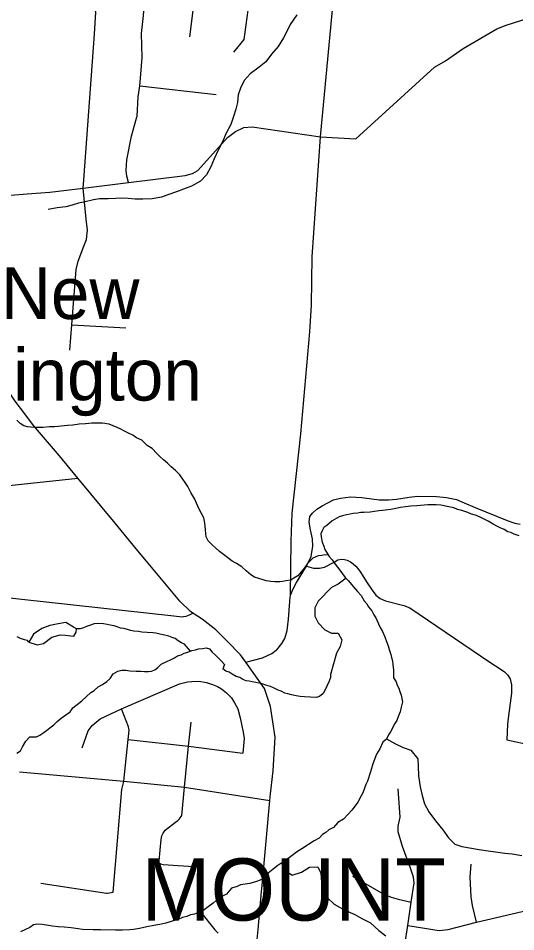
# Model space of a CAD drawing. Extents: x 0 to 69.5, y -4.5 to 22.
# Drawn here: x 6.214 to 6.973, y 17.057 to 18.449 of the extents above; entities that cross this region are included whole.
import ezdxf

# ---------------------------------------------------------------- set-up
doc = ezdxf.new("R2010")
doc.units = 0
for name, color, linetype in [('GM_X_Corporation_Text', 7, 'Continuous'), ('GM_X_County_Road', 7, 'Continuous'), ('GM_X_Minor_Lake', 7, 'Continuous'), ('GM_X_Minor_River', 7, 'Continuous'), ('GM_X_Township_Subdivision', 7, 'Continuous'), ('GM_X_Unincorporated_Text', 7, 'Continuous'), ('GM_X_US_Route', 7, 'Continuous')]:
    doc.layers.add(name, color=color, linetype=linetype)

msp = doc.modelspace()

# ---------------------------------------------------------------- linework, layer by layer
at = {"layer": 'GM_X_County_Road'}
for points in [[(6.6289, 17.5702), (6.6299, 17.6523), (6.6319, 17.6948), (6.6451, 17.8156), (6.6585, 17.9713), (6.6613, 18.0126), (6.6624, 18.0856), (6.6748, 18.2683), (6.7103, 18.6453), (6.7239, 18.8027), (6.734, 18.8917), (6.7405, 19.0079)], [(6.6748, 18.2683), (6.7285, 18.2655), (6.8486, 18.3747), (6.8655, 18.3843), (6.8923, 18.4031), (6.9436, 18.4327), (6.9578, 18.4383), (6.9913, 18.4492), (7.0954, 18.4834), (7.0971, 18.484)], [(6.063, 18.1333), (6.1136, 18.1511), (6.1283, 18.1584), (6.17, 18.1715), (6.2024, 18.1796), (6.2275, 18.1814), (6.2621, 18.1839), (6.3129, 18.1902), (6.3819, 18.1988), (6.4683, 18.2096), (6.4798, 18.2126), (6.4879, 18.217), (6.533, 18.2673), (6.545, 18.2764), (6.5577, 18.2825), (6.5706, 18.2836), (6.6748, 18.2683)], [(6.6282, 17.5603), (6.6283, 17.5621), (6.6289, 17.5702), (6.633, 17.5796), (6.6382, 17.5893), (6.6534, 17.6142), (6.6608, 17.6291), (6.663, 17.6446), (6.6626, 17.6559), (6.6596, 17.6696), (6.6576, 17.6814), (6.6584, 17.6899), (6.6626, 17.695), (6.6695, 17.7008), (6.6773, 17.7062), (6.6946, 17.7151), (6.7055, 17.7177), (6.7206, 17.7197), (6.738, 17.7187), (6.7642, 17.7153), (6.7787, 17.7154), (6.7909, 17.7162), (6.81, 17.7191), (6.8227, 17.7208), (6.8517, 17.7202), (6.8672, 17.7188), (6.8821, 17.7156), (6.8941, 17.7107), (6.9106, 17.7038), (6.9593, 17.6839), (6.9714, 17.6796), (6.9791, 17.6783)], [(5.5312, 17.5084), (5.5691, 17.507), (5.6976, 17.4979), (5.7449, 17.494), (5.7812, 17.4914), (5.8077, 17.4899), (5.8238, 17.4905), (5.8392, 17.4936), (5.8617, 17.5004), (5.9034, 17.5131), (5.9959, 17.5435), (6.0061, 17.5479), (6.0184, 17.5562), (6.041, 17.5742), (6.0478, 17.5777), (6.0541, 17.5801), (6.0612, 17.5813), (6.0695, 17.5816), (6.1446, 17.5721), (6.4513, 17.5386)], [(6.607, 17.486), (6.6073, 17.4862), (6.6082, 17.4869), (6.6157, 17.4962), (6.6204, 17.504), (6.6242, 17.5161), (6.6263, 17.5335), (6.6282, 17.5603)], [(6.4513, 17.5386), (6.4638, 17.5372), (6.4661, 17.5373), (6.47, 17.538), (6.4727, 17.5389), (6.4763, 17.5404), (6.4804, 17.5426)], [(6.5612, 17.4679), (6.5866, 17.4743), (6.6008, 17.481), (6.607, 17.486)]]:
    msp.add_lwpolyline(points, dxfattribs=at)
at = {"layer": 'GM_X_Minor_Lake'}
for points in [[(6.3028, 17.5185), (6.2984, 17.5211), (6.2864, 17.5282), (6.2746, 17.5262), (6.262, 17.5238), (6.2501, 17.5191), (6.237, 17.5106), (6.2303, 17.4982), (6.2428, 17.4945), (6.2523, 17.4966), (6.2651, 17.5058)], [(6.2651, 17.5058), (6.2777, 17.5098), (6.2857, 17.5092), (6.2989, 17.5074), (6.3021, 17.5134), (6.3028, 17.5185)]]:
    msp.add_lwpolyline(points, dxfattribs=at)
at = {"layer": 'GM_X_Minor_River'}
for points in [[(6.639, 18.4543), (6.6288, 18.4397), (6.6237, 18.4291), (6.6185, 18.419), (6.6103, 18.4059), (6.6002, 18.3943), (6.5916, 18.3827), (6.5812, 18.3745), (6.5676, 18.3642), (6.5583, 18.3541), (6.5528, 18.3424), (6.5491, 18.3322), (6.5481, 18.3205), (6.5456, 18.3107), (6.542, 18.2993), (6.5379, 18.2873), (6.5304, 18.273), (6.526, 18.262), (6.5181, 18.247), (6.5129, 18.2349), (6.5077, 18.2225), (6.501, 18.2105), (6.4921, 18.2008), (6.4779, 18.1931), (6.466, 18.1884), (6.4553, 18.1844), (6.4423, 18.1798), (6.4323, 18.1762), (6.4182, 18.1738), (6.4038, 18.1733), (6.3924, 18.1736), (6.3814, 18.1742), (6.3719, 18.1747), (6.3624, 18.1742), (6.3513, 18.174), (6.338, 18.1739), (6.3285, 18.1722), (6.3159, 18.1694), (6.3056, 18.1674), (6.296, 18.1641), (6.2865, 18.1617), (6.2732, 18.16), (6.2594, 18.1577)], [(6.6867, 17.6307), (6.6814, 17.6312), (6.6768, 17.6305), (6.6711, 17.6299), (6.6631, 17.6262), (6.6549, 17.618), (6.6506, 17.6116), (6.646, 17.606), (6.6401, 17.5993), (6.6344, 17.596), (6.6298, 17.593), (6.6221, 17.5917), (6.6176, 17.591), (6.6126, 17.5903), (6.6054, 17.5901), (6.599, 17.5906), (6.5922, 17.5919), (6.5873, 17.5935), (6.5744, 17.5976), (6.5684, 17.6011), (6.5613, 17.6069), (6.555, 17.6132), (6.5468, 17.6183), (6.5404, 17.6218), (6.5355, 17.6253), (6.531, 17.6289), (6.5206, 17.6367), (6.5146, 17.6421), (6.5101, 17.6464), (6.5034, 17.653), (6.5005, 17.6591), (6.4996, 17.669), (6.499, 17.6755), (6.498, 17.6828), (6.4969, 17.6877), (6.4933, 17.6946), (6.4896, 17.7012), (6.486, 17.71), (6.4831, 17.7162), (6.4802, 17.7215), (6.4772, 17.7265), (6.4728, 17.7354), (6.4684, 17.7415), (6.4647, 17.7469), (6.4603, 17.7535), (6.4536, 17.7601), (6.4469, 17.7656), (6.4413, 17.771), (6.4353, 17.7764), (6.4301, 17.7811), (6.4253, 17.7858), (6.4182, 17.7935), (6.4107, 17.7979), (6.4022, 17.8064), (6.3943, 17.8096), (6.3887, 17.8139), (6.3819, 17.8167), (6.3762, 17.8198), (6.3702, 17.823), (6.365, 17.8254), (6.3526, 17.8306), (6.3423, 17.8319), (6.3359, 17.8321), (6.326, 17.8319), (6.3214, 17.8316), (6.3165, 17.8313), (6.307, 17.8304), (6.2971, 17.829), (6.2891, 17.8284), (6.2842, 17.8278), (6.275, 17.8272), (6.2693, 17.8265), (6.2617, 17.8263), (6.2519, 17.8257), (6.2443, 17.8255), (6.239, 17.8256), (6.2333, 17.8261), (6.228, 17.8266), (6.2223, 17.8282), (6.2171, 17.8318), (6.2118, 17.8364)], [(6.9777, 17.6602), (6.9702, 17.663), (6.9653, 17.6654), (6.9604, 17.6667), (6.9547, 17.6698), (6.9491, 17.6726), (6.9446, 17.6746), (6.9382, 17.6781), (6.9307, 17.6825), (6.9254, 17.6852), (6.9206, 17.688), (6.9127, 17.6912), (6.9051, 17.6936), (6.8995, 17.696), (6.8904, 17.6992), (6.884, 17.7005), (6.878, 17.7029), (6.8704, 17.7046), (6.8583, 17.7071), (6.8515, 17.7076), (6.8432, 17.7078), (6.8386, 17.7075), (6.8329, 17.7072), (6.8219, 17.7059), (6.8127, 17.7054), (6.8044, 17.7044), (6.7968, 17.7034), (6.7895, 17.702), (6.7819, 17.7007), (6.7773, 17.7), (6.7693, 17.699), (6.7636, 17.6987), (6.7507, 17.6967), (6.7408, 17.6962), (6.7362, 17.6959), (6.7313, 17.6948), (6.7248, 17.6942), (6.7199, 17.6932), (6.7145, 17.6925), (6.7084, 17.6907), (6.7031, 17.6893), (6.6927, 17.6834), (6.6846, 17.6764), (6.68, 17.673), (6.6776, 17.6681), (6.6756, 17.6632), (6.6759, 17.6587), (6.6773, 17.651), (6.6798, 17.6449), (6.6816, 17.6395), (6.6882, 17.6287), (6.6926, 17.6237), (6.6956, 17.6191), (6.7008, 17.6129), (6.7045, 17.6083), (6.7126, 17.5971), (6.7178, 17.592), (6.7248, 17.5831), (6.7311, 17.5758), (6.7367, 17.5696), (6.7415, 17.5615), (6.7456, 17.5569), (6.7481, 17.5522), (6.7529, 17.5461), (6.7562, 17.5399), (6.7592, 17.5353), (6.7632, 17.5265), (6.7661, 17.5207), (6.7694, 17.5145), (6.773, 17.5065), (6.7755, 17.4996), (6.778, 17.4927), (6.7798, 17.4873), (6.782, 17.4797), (6.783, 17.4751), (6.7848, 17.4697), (6.7851, 17.4636), (6.786, 17.4564)], [(6.714, 17.5957), (6.702, 17.5866), (6.6918, 17.5815), (6.6713, 17.561), (6.6661, 17.5507), (6.6661, 17.5379), (6.6713, 17.5276), (6.6815, 17.5174), (6.6918, 17.5122), (6.702, 17.5122), (6.7072, 17.502), (6.7046, 17.4917), (6.6995, 17.4814), (6.6902, 17.449)], [(6.4765, 17.4848), (6.4676, 17.4955), (6.4631, 17.4975), (6.4578, 17.5006), (6.4533, 17.5038), (6.4488, 17.5057), (6.4435, 17.5074), (6.4349, 17.5098), (6.4299, 17.5107), (6.4239, 17.5119), (6.4194, 17.5124), (6.4106, 17.513), (6.4023, 17.5135), (6.3974, 17.5144), (6.3902, 17.5153), (6.3853, 17.5161), (6.3804, 17.5178), (6.3747, 17.519), (6.3698, 17.5199), (6.3649, 17.5219), (6.36, 17.5235), (6.3543, 17.5244), (6.3494, 17.5252), (6.3437, 17.5261), (6.3369, 17.5266), (6.3297, 17.5264), (6.3224, 17.5239), (6.3178, 17.5224), (6.3132, 17.5202), (6.3083, 17.5188), (6.3033, 17.5185), (6.3028, 17.5185)], [(6.2303, 17.4982), (6.2278, 17.501), (6.2233, 17.5019), (6.2172, 17.5039), (6.2124, 17.5067)], [(6.4317, 17.465), (6.4413, 17.4694), (6.4462, 17.4716), (6.452, 17.4745), (6.457, 17.4774), (6.4623, 17.4792), (6.4669, 17.4814), (6.4723, 17.4832), (6.4788, 17.4857), (6.4841, 17.4868), (6.4887, 17.4882), (6.4948, 17.4889), (6.5005, 17.4895), (6.5054, 17.4883), (6.5095, 17.4832), (6.5143, 17.4793), (6.5244, 17.4689), (6.5285, 17.4642), (6.5258, 17.4578)], [(6.786, 17.4564), (6.7863, 17.444), (6.7903, 17.4378), (6.7917, 17.4328), (6.7942, 17.4282), (6.7956, 17.4232), (6.7977, 17.4178), (6.7987, 17.4128), (6.7997, 17.4075), (6.798, 17.3992), (6.7963, 17.3924), (6.7938, 17.3863), (6.7914, 17.3788), (6.7882, 17.3743), (6.7814, 17.3619), (6.7786, 17.3574), (6.7754, 17.3507), (6.7699, 17.3462), (6.7651, 17.3361), (6.7603, 17.3279), (6.7546, 17.3132), (6.7512, 17.3007), (6.7463, 17.2864), (6.7442, 17.2815), (6.7393, 17.2687), (6.7369, 17.2642), (6.7317, 17.2548), (6.7234, 17.2428), (6.7097, 17.2287), (6.7012, 17.2236), (6.6945, 17.2162), (6.6876, 17.2126), (6.6829, 17.2082), (6.6779, 17.2053), (6.6728, 17.1997), (6.6651, 17.1957), (6.6465, 17.1837), (6.6384, 17.1782), (6.6318, 17.1734), (6.6221, 17.1661), (6.6097, 17.158), (6.605, 17.1544), (6.5949, 17.1463), (6.5898, 17.1392), (6.5828, 17.1359), (6.5771, 17.1338), (6.5671, 17.1307), (6.553, 17.1284), (6.5476, 17.1263), (6.5391, 17.1235), (6.5313, 17.1145), (6.5201, 17.1088), (6.5111, 17.1006), (6.5034, 17.0951), (6.4952, 17.0889), (6.4829, 17.0839), (6.4764, 17.0829), (6.471, 17.0804), (6.4642, 17.0791), (6.458, 17.0758), (6.45, 17.0738), (6.4392, 17.0703), (6.43, 17.0682), (6.4209, 17.0666), (6.4098, 17.0646), (6.399, 17.0619), (6.3899, 17.0606), (6.3842, 17.06), (6.3727, 17.0596), (6.3621, 17.0595), (6.3393, 17.0601), (6.3283, 17.06), (6.3119, 17.0605), (6.3055, 17.0614), (6.2945, 17.0633), (6.2839, 17.0639), (6.2748, 17.0646), (6.2664, 17.0656), (6.26, 17.0665), (6.2502, 17.0683), (6.2422, 17.0689), (6.2372, 17.0675), (6.2314, 17.0635), (6.2175, 17.057)], [(6.2866, 17.3876), (6.2932, 17.3923), (6.2971, 17.3983), (6.3037, 17.4034), (6.3107, 17.409), (6.3244, 17.4219), (6.3298, 17.4248), (6.336, 17.4303), (6.3426, 17.434), (6.3488, 17.4387), (6.3539, 17.4432), (6.3586, 17.4499), (6.366, 17.4543), (6.3717, 17.4556), (6.3778, 17.4558), (6.3842, 17.4549), (6.3937, 17.4542), (6.4009, 17.454), (6.4066, 17.4535), (6.4127, 17.4537), (6.4173, 17.4544), (6.4223, 17.4561), (6.427, 17.4598), (6.4317, 17.465)], [(6.6902, 17.449), (6.6901, 17.4444), (6.688, 17.4388), (6.6844, 17.4313), (6.682, 17.426), (6.6788, 17.4204), (6.6733, 17.4156), (6.6687, 17.4142), (6.6596, 17.4144), (6.6505, 17.4151), (6.6437, 17.4157), (6.638, 17.4166), (6.6304, 17.4179), (6.6251, 17.4196), (6.6206, 17.4205), (6.615, 17.4237), (6.6101, 17.4254), (6.6033, 17.429), (6.5988, 17.4306), (6.5917, 17.4327), (6.586, 17.4348), (6.5807, 17.4361), (6.5762, 17.437), (6.5709, 17.4379), (6.5663, 17.4388), (6.5614, 17.4397), (6.5562, 17.4417), (6.5517, 17.4445), (6.546, 17.4462), (6.54, 17.4498), (6.5355, 17.4526), (6.5303, 17.4542), (6.5258, 17.4578)], [(6.2116, 17.3291), (6.2174, 17.3327), (6.2202, 17.3391), (6.2254, 17.3477), (6.2317, 17.354), (6.2362, 17.3539), (6.2419, 17.3541), (6.247, 17.3567), (6.2516, 17.3596), (6.257, 17.364), (6.2621, 17.3677), (6.2683, 17.3724), (6.2734, 17.3773), (6.2796, 17.3828), (6.2866, 17.3876)], [(6.7756, 17.3511), (6.789, 17.3433), (6.8011, 17.3378), (6.8128, 17.3337), (6.8235, 17.3206), (6.8236, 17.3095), (6.8245, 17.2947), (6.8267, 17.2779), (6.8299, 17.2646), (6.8334, 17.252), (6.84, 17.2397), (6.8503, 17.2261), (6.8614, 17.2126), (6.8703, 17.2003), (6.8795, 17.1906), (6.8905, 17.1869), (6.917, 17.1825), (6.9306, 17.1803), (6.9416, 17.179), (6.956, 17.1771), (6.9674, 17.1757), (6.9821, 17.1735)], [(6.6154, 17.1618), (6.6219, 17.1502), (6.6316, 17.1435), (6.6461, 17.1477), (6.6581, 17.1555), (6.671, 17.1563), (6.6753, 17.1464), (6.6766, 17.1326), (6.6804, 17.1189), (6.6859, 17.1081), (6.6956, 17.0992), (6.7121, 17.0901), (6.7272, 17.0833), (6.7377, 17.0774), (6.7512, 17.0706), (6.7639, 17.0593), (6.7743, 17.0511)], [(6.4918, 17.0875), (6.5135, 17.0602), (6.519, 17.0551)]]:
    msp.add_lwpolyline(points, dxfattribs=at)
at = {"layer": 'GM_X_Township_Subdivision'}
for points in [[(6.3138, 18.2028), (6.3304, 18.425), (6.3322, 18.4584), (6.3274, 18.4859)], [(6.4018, 18.3765), (6.403, 18.3892), (6.4017, 18.4257), (6.4051, 18.4532), (6.4066, 18.4741), (6.4072, 18.4851), (6.4112, 18.4906), (6.4207, 18.4906), (6.4366, 18.4888), (6.4562, 18.4863), (6.4832, 18.4817), (6.5659, 18.4725), (6.5944, 18.4771)], [(6.4758, 18.4205), (6.4832, 18.4817)], [(6.5429, 18.3975), (6.5583, 18.4168), (6.5659, 18.4725)], [(6.3944, 18.2969), (6.3953, 18.2999), (6.397, 18.3293), (6.3991, 18.3459), (6.4013, 18.3699), (6.4018, 18.3765)], [(6.3991, 18.3459), (6.5156, 18.3328)], [(6.3819, 18.1988), (6.3795, 18.2083), (6.3787, 18.2169), (6.3795, 18.2334), (6.3866, 18.2693), (6.3915, 18.2879), (6.3933, 18.2934), (6.3944, 18.2969)], [(6.2927, 17.9432), (6.2957, 17.9819), (6.3025, 18.0664), (6.3051, 18.0789), (6.3138, 18.1018), (6.3179, 18.1119), (6.3194, 18.1259), (6.3177, 18.1431), (6.3129, 18.1902), (6.3138, 18.2028), (6.3138, 18.2028)], [(6.2957, 17.9819), (6.3778, 17.9775)], [(6.022, 17.7199), (6.0333, 17.7203), (6.0558, 17.7219), (6.305, 17.7484)], [(6.6534, 17.6142), (6.6641, 17.611), (6.6733, 17.6109), (6.6812, 17.6129), (6.6957, 17.6204), (6.7014, 17.6238), (6.707, 17.6247), (6.7113, 17.6242), (6.7153, 17.6231), (6.7208, 17.6209), (6.7249, 17.6176), (6.7287, 17.6142), (6.7318, 17.6105), (6.7357, 17.6052), (6.7448, 17.5901), (6.7534, 17.5774), (6.7593, 17.5701), (6.7657, 17.5649), (6.774, 17.5616), (6.8017, 17.5545), (6.811, 17.5506), (6.9333, 17.468), (6.949, 17.4576), (6.9557, 17.4533), (6.9602, 17.4488), (6.9641, 17.4423), (6.966, 17.4334), (6.9663, 17.4208), (6.9605, 17.3786)], [(6.3116, 17.3375), (6.3208, 17.3633), (6.3268, 17.3712), (6.3389, 17.3814), (6.3713, 17.3969), (6.4596, 17.4348), (6.4721, 17.4381), (6.4784, 17.4387), (6.4894, 17.4388), (6.5012, 17.4371), (6.5103, 17.4341), (6.5176, 17.431), (6.5239, 17.4271), (6.5317, 17.4211), (6.539, 17.4137), (6.5439, 17.4061), (6.5488, 17.3969), (6.5523, 17.3829), (6.557, 17.3613), (6.5583, 17.3518), (6.5565, 17.3292)], [(6.3742, 17.2843), (6.3747, 17.2864), (6.3817, 17.3502), (6.3823, 17.3546), (6.383, 17.3642), (6.3822, 17.3696), (6.3713, 17.3969)], [(6.4887, 17.1557), (6.4348, 17.1593), (6.4308, 17.1599), (6.4289, 17.1618), (6.4287, 17.1653), (6.432, 17.1977), (6.4331, 17.2031), (6.4351, 17.2074), (6.4382, 17.2119), (6.4537, 17.2239), (6.4572, 17.2269), (6.4598, 17.2292), (6.4634, 17.2344), (6.4676, 17.2776), (6.4737, 17.3397), (6.4774, 17.3767)], [(6.9605, 17.3786), (6.9598, 17.3731), (6.9592, 17.3497)], [(6.3817, 17.3502), (6.4737, 17.3397), (6.5565, 17.3292)], [(6.9592, 17.3497), (6.997, 17.3415), (7.0662, 17.3297), (7.0999, 17.3233)], [(6.216, 17.3009), (6.3747, 17.2864), (6.4676, 17.2776), (6.5974, 17.257)], [(6.3586, 17.1174), (6.3719, 17.2737), (6.3742, 17.2843)], [(6.7844, 16.9112), (6.7902, 16.9495), (6.799, 17.0076), (6.8079, 17.0668), (6.8133, 17.1023), (6.8178, 17.1319), (6.8167, 17.1402), (6.8123, 17.154), (6.8001, 17.1868), (6.7932, 17.2092), (6.7932, 17.218), (6.7964, 17.2316), (6.7931, 17.275)], [(6.9126, 17.0718), (6.9066, 17.0971), (6.9044, 17.1101), (6.9031, 17.1405), (6.9045, 17.1601)], [(6.7238, 17.1416), (6.7702, 17.1147), (6.7826, 17.11), (6.7935, 17.1067), (6.8133, 17.1023)], [(6.2483, 17.1314), (6.3486, 17.116)], [(6.8079, 17.0668), (6.8559, 17.059), (6.8697, 17.0604), (6.9126, 17.0718), (6.9976, 17.0915), (7.0535, 17.1074), (7.0787, 17.1167), (7.0879, 17.1194), (7.1083, 17.126), (7.1159, 17.1268), (7.1214, 17.127), (7.1302, 17.1268), (7.1611, 17.1219), (7.2871, 17.0984), (7.3191, 17.0935)], [(6.3486, 17.116), (6.3502, 17.1157), (6.3586, 17.1174)]]:
    msp.add_lwpolyline(points, dxfattribs=at)
at = {"layer": 'GM_X_US_Route'}
for points in [[(6.3964, 17.6376), (6.3615, 17.6796), (6.305, 17.7484), (6.277, 17.7824), (6.2372, 17.8287), (6.224, 17.8461), (6.2093, 17.8655), (6.1706, 17.9227), (6.1378, 17.9744), (6.1043, 18.0396)], [(6.5857, 17.1275), (6.5974, 17.257), (6.5985, 17.2671), (6.6027, 17.3024), (6.6056, 17.3535), (6.5985, 17.4006), (6.5894, 17.4276), (6.5612, 17.4679), (6.5528, 17.4791), (6.5325, 17.4997), (6.5155, 17.5173), (6.4943, 17.5334), (6.4804, 17.5426), (6.4764, 17.5452), (6.4601, 17.5608), (6.4096, 17.6217), (6.3964, 17.6376)], [(6.5713, 16.9682), (6.5773, 17.0352), (6.5796, 17.0608), (6.5848, 17.1183), (6.5857, 17.1275)]]:
    msp.add_lwpolyline(points, dxfattribs=at)

# ---------------------------------------------------------------- texts
at = {"layer": 'GM_X_Corporation_Text'}
msp.add_text('MOUNT', height=0.0947, rotation=0, dxfattribs=at).set_placement((6.4017, 17.0742))
at = {"layer": 'GM_X_Unincorporated_Text'}
for s, p in [('New', (6.1875, 17.9907)), ('Burlington', (6.0184, 17.8665))]:
    msp.add_text(s, height=0.07898, rotation=0, dxfattribs=at).set_placement(p)

doc.saveas('drawing.dxf')
